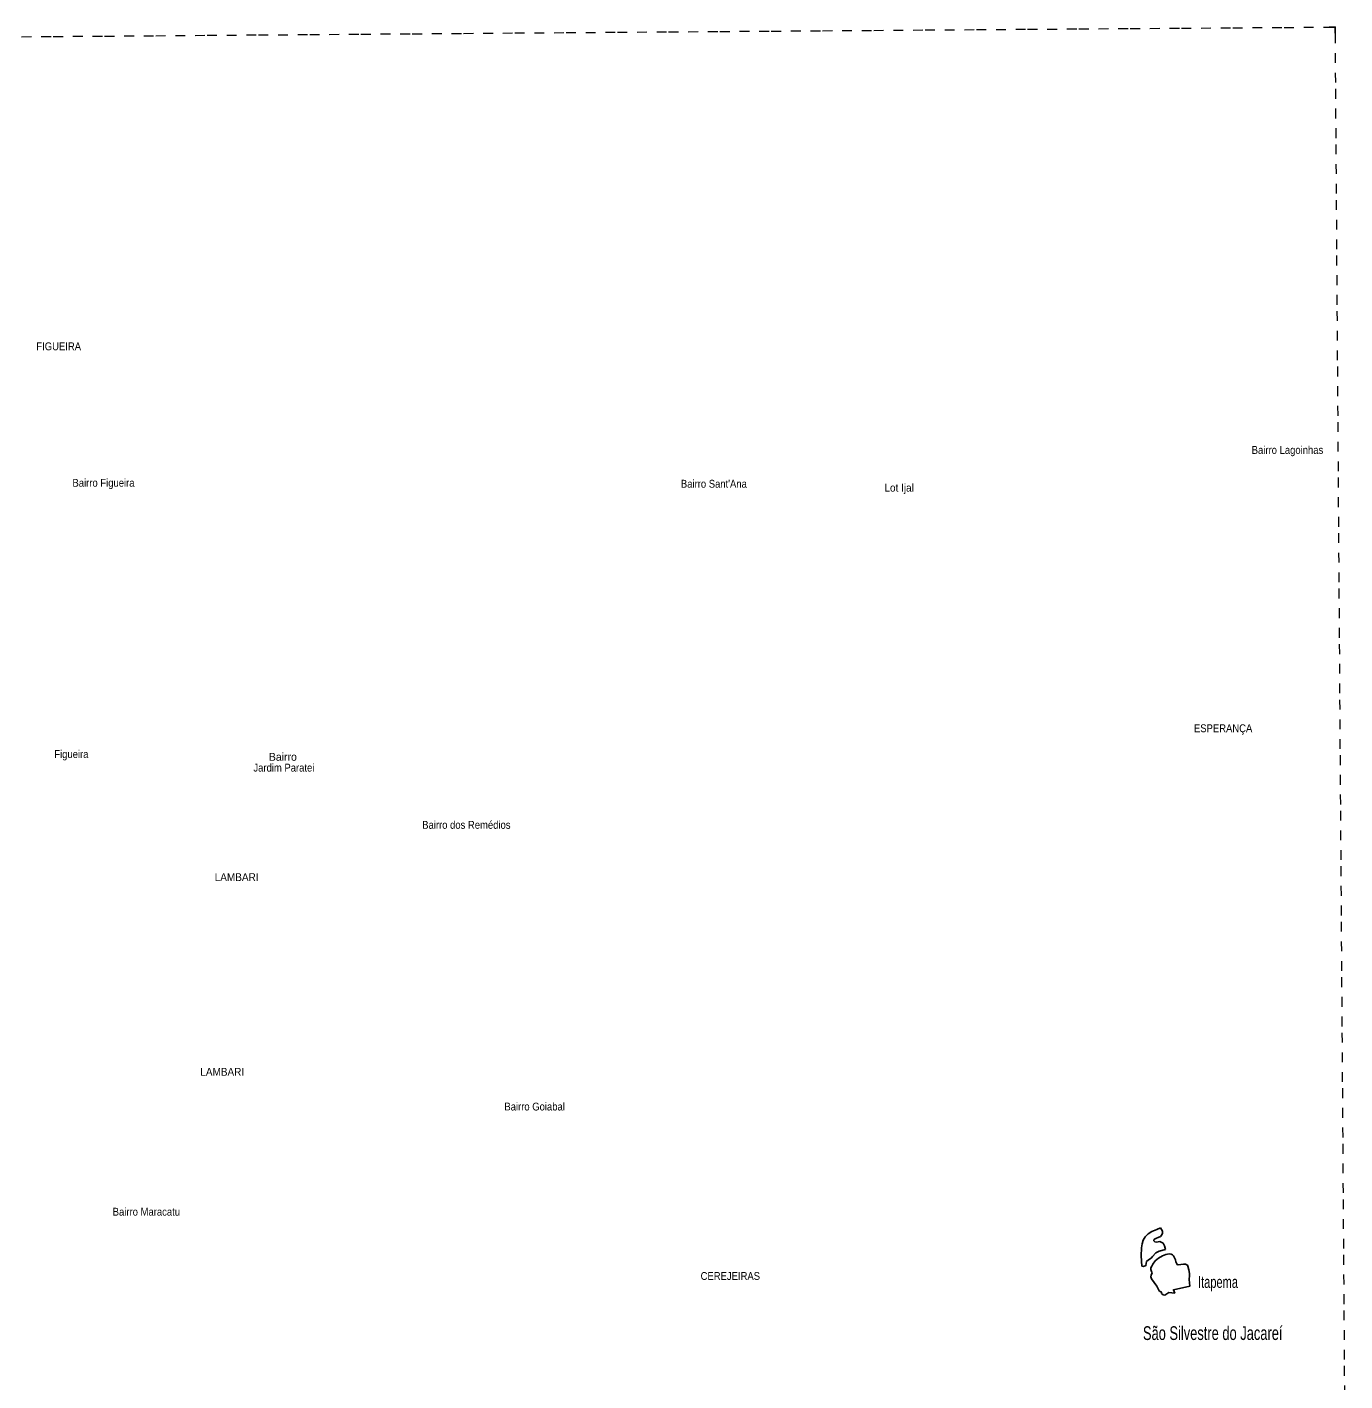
# Model space of a CAD drawing. Extents: x 372.1 to 397.9, y 7400.6 to 7428.4.
# Drawn here: x 384.39 to 397.8, y 7414.67 to 7428.44 of the extents above; entities that cross this region are included whole.
import ezdxf
from ezdxf.enums import TextEntityAlignment as Align

# ---------------------------------------------------------------- set-up
doc = ezdxf.new("R2010")
doc.units = 0
doc.header["$LTSCALE"] = 0.032
doc.linetypes.add('SHORT_DASHED', pattern=[2.7, 1.5, -1.2])
for name, color, linetype, lineweight in [('41', 7, 'Continuous', 25), ('46', 7, 'SHORT_DASHED', 13), ('63', 7, 'Continuous', 25)]:
    doc.layers.add(name, color=color, linetype=linetype, lineweight=lineweight)
doc.layers.add('61', color=7, linetype='Continuous')

msp = doc.modelspace()

# ---------------------------------------------------------------- linework, layer by layer
at = {"layer": '41'}
for points in [[(395.9237, 7416.226), (395.8858, 7416.208), (395.8366, 7416.1908), (395.7986, 7416.1666), (395.7701, 7416.1338), (395.7494, 7416.0997), (395.7365, 7416.0644), (395.7313, 7416.0247), (395.7287, 7415.9422), (395.7341, 7415.8352)], [(395.976, 7416.0066), (395.9637, 7416.0428), (395.9501, 7416.0699), (395.917, 7416.0871), (395.8851, 7416.0824), (395.8683, 7416.0847), (395.8579, 7416.0943), (395.8579, 7416.1047), (395.8627, 7416.1127), (395.8851, 7416.1231), (395.9018, 7416.1271), (395.9234, 7416.1391), (395.937, 7416.1537), (395.9465, 7416.1707), (395.9436, 7416.193), (395.9237, 7416.226)], [(395.8339, 7415.9217), (395.8424, 7415.9349), (395.876, 7415.9706), (395.9116, 7415.9905), (395.976, 7416.0066)], [(395.7341, 7415.8352), (395.7529, 7415.8339), (395.7765, 7415.8423), (395.783, 7415.8855)], [(395.783, 7415.8855), (395.8036, 7415.8997), (395.8302, 7415.9192), (395.8339, 7415.9217)], [(395.8478, 7415.8568), (395.8352, 7415.8369), (395.8278, 7415.818), (395.8268, 7415.8043), (395.832, 7415.7833), (395.8404, 7415.77)], [(396.0451, 7415.9523), (396.0325, 7415.9597), (396.0115, 7415.9613), (395.98, 7415.955), (395.9464, 7415.9413), (395.9044, 7415.9193), (395.8876, 7415.9056), (395.8698, 7415.8899), (395.8478, 7415.8568)], [(396.1039, 7415.8515), (396.0988, 7415.8501), (396.0913, 7415.861), (396.0808, 7415.8799), (396.0766, 7415.9009), (396.0682, 7415.9219), (396.0567, 7415.9418), (396.0451, 7415.9523)], [(396.1995, 7415.8463), (396.1795, 7415.8578), (396.1585, 7415.8568), (396.1039, 7415.8515)], [(395.8404, 7415.77), (395.8295, 7415.7463), (395.8267, 7415.7284), (395.8315, 7415.706), (395.8866, 7415.6325), (395.91, 7415.5851), (395.9198, 7415.5771), (395.9344, 7415.5726), (395.936, 7415.5587)], [(395.936, 7415.5587), (395.9524, 7415.545), (395.969, 7415.5414), (396.0082, 7415.569), (396.0702, 7415.5627), (396.0562, 7415.5971), (396.2236, 7415.6331), (396.2173, 7415.7019), (396.2194, 7415.7428), (396.2194, 7415.7607)], [(396.2194, 7415.7607), (396.2141, 7415.7995), (396.2026, 7415.8363), (396.1995, 7415.8463)]]:
    msp.add_lwpolyline(points, dxfattribs=at)
at = {"layer": '46'}
for points in [[(384.1332, 7428.3438), (384.6551, 7428.3479), (385.1771, 7428.3519), (385.6991, 7428.3559), (386.221, 7428.36), (386.743, 7428.364), (387.265, 7428.3679), (387.7869, 7428.3719), (388.3089, 7428.3758), (388.8309, 7428.3797), (389.3528, 7428.3836), (389.8748, 7428.3875), (390.3967, 7428.3914), (390.9187, 7428.3952), (391.4407, 7428.399), (391.9626, 7428.4029), (392.4846, 7428.4066), (393.0065, 7428.4104), (393.5285, 7428.4142), (394.0505, 7428.4179), (394.5724, 7428.4216), (395.0944, 7428.4253), (395.6163, 7428.429), (396.1383, 7428.4327), (396.6602, 7428.4363), (397.1822, 7428.4399), (397.7042, 7428.4435)], [(397.8017, 7414.3216), (397.7978, 7414.8864), (397.7939, 7415.4513), (397.79, 7416.0162), (397.7861, 7416.5811), (397.7822, 7417.146), (397.7783, 7417.7109), (397.7743, 7418.2757), (397.7704, 7418.8406), (397.7665, 7419.4055), (397.7626, 7419.9704), (397.7587, 7420.5353), (397.7548, 7421.1001), (397.7509, 7421.665), (397.747, 7422.2299), (397.7431, 7422.7948), (397.7392, 7423.3596), (397.7353, 7423.9245), (397.7314, 7424.4894), (397.7275, 7425.0543), (397.7236, 7425.6191), (397.7197, 7426.184), (397.7158, 7426.7489), (397.7119, 7427.3138), (397.708, 7427.8786), (397.7042, 7428.4435)]]:
    msp.add_lwpolyline(points, dxfattribs=at)
at = {"layer": '63'}
msp.add_lwpolyline([(397.7028, 7428.382), (397.7028, 7428.4436), (397.6421, 7428.4436)], dxfattribs=at)

# ---------------------------------------------------------------- texts
at = {"layer": '61'}
for s, width, p in [('FIGUEIRA', 0.9, (384.7105, 7425.1554)), ('ESPERANÇA', 0.9, (396.562, 7421.2694)), ('LAMBARI', 0.95, (386.5215, 7419.7548)), ('LAMBARI', 0.95, (386.3749, 7417.774)), ('CEREJEIRAS', 0.9, (391.5462, 7415.6966))]:
    msp.add_text(s, height=0.08, dxfattribs=dict(at, width=width)).set_placement(p, align=Align.CENTER)
for s, height, width, p in [('Bairro Lagoinhas', 0.08, 0.9, (396.853, 7424.1011)), ("Bairro Sant'Ana", 0.08, 0.9, (391.0433, 7423.7571)), ('Bairro dos Remédios', 0.08, 0.9, (388.4103, 7420.2866)), ('Bairro Maracatu', 0.08, 0.9, (385.2603, 7416.3504)), ('Itapema', 0.12, 0.7, (396.307, 7415.6153)), ('São Silvestre do Jacareí', 0.14, 0.7, (395.7459, 7415.0854))]:
    msp.add_text(s, height=height, dxfattribs=dict(at, width=width)).set_placement(p)
for s, width, p in [('Bairro Figueira', 0.9, (385.4823, 7423.767)), ('Lot Ijal', 0.95, (393.4142, 7423.717)), ('Figueira', 0.9, (385.0134, 7421.0066)), ('Jardim Paratei', 0.9, (387.313, 7420.8686)), ('Bairro Goiabal', 0.9, (389.8621, 7417.4205))]:
    msp.add_text(s, height=0.08, dxfattribs=dict(at, width=width)).set_placement(p, align=Align.RIGHT)
msp.add_text('Bairro      ', height=0.08, dxfattribs=at).set_placement((387.313, 7420.9786), align=Align.RIGHT)

doc.saveas('drawing.dxf')
